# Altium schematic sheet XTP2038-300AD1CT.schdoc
size 127 x 101 mm
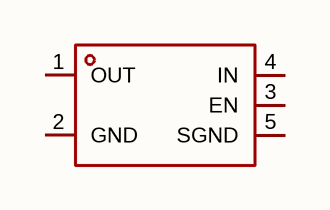
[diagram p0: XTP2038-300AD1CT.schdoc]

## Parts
U?  xtp2038-300ad1ct  [UDFN-4_L1.0-W1.0-P0.65-TL]  (value not drawn)

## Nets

Not connected (* = marked no-connect by the designer): U? 1(OUT) 2(GND) 3(EN) 4(IN) 5(SGND)

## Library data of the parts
U? = xtp2038-300ad1ct: 输出极性:正极;工作电压:5.5V;输出电压:3V;输出电流:500mA;电源纹波抑制比(PSRR):-;输出类型:固定;; Manufacturer: XTX(芯天下); AddInBom: yes; ModelId: 9c2eebc267f642aab45e7193d1ab7813; ModelTransform: 40.1574,39.37394,0,0,0,0,0,0,0; Output Configuration: 正极; Voltage - Supply: 5.5V; Output Voltage: 3V; Output Current: 500mA; Voltage Dropout: 180mV@(300mA); standby current: 15uA; Output Type: 固定; Number of Outputs: 1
